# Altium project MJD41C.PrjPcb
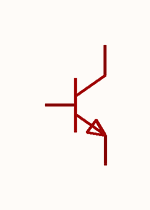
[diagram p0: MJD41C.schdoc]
1 sheet, 1 parts. Net scope: global (net labels, ports and power ports of the same name join across sheets).

## Sheet MJD41C.schdoc
size 127 x 101 mm

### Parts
Q?  mjd41c  [TO-252-2_L6.6-W6.1-P4.57-LS9.9-TR-CW]  (value not drawn)

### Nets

Not connected (* = marked no-connect by the designer): Q? 1(B) 2(C) 3(E)

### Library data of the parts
Q? = mjd41c: 晶体管类型:NPN;集电极电流(Ic):9A;集射极击穿电压(Vceo):100V;耗散功率(Pd):1.25W;直流电流增益(hFE):30;; Manufacturer: CJ(江苏长电/长晶); AddInBom: yes; ModelId: ce57f84d66384067af8a68020b6de06d; ModelName: TO-252-2L-3P_L6.6-W6.1-H2.3-LS10.1-P4.6; ModelTransform: 259.842,390.52442,0,180,0,0,-0.118,-43.303,0; type: NPN; Current - Collector(Ic): 9A; Collector - Emitter Voltage VCEO: 100V; Pd - Power Dissipation: 1.25W; DC Current Gain: 30; Transition frequency(fT): 3MHz; Current - Collector Cutoff: 50uA; Vce Saturation(VCE(sat)): 1.5V; Emitter-Base Voltage(Vebo): 5V; Number: 1个NPN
